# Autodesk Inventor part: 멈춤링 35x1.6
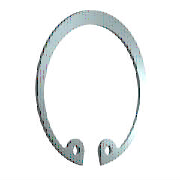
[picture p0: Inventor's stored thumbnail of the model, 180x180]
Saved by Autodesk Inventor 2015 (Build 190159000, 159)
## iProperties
IsCustomPart: 1
Created: 2012-02
Part Number: 멈춤링 35x1.6
Material: 강철, 연강
Description: 리테이닝 링(C형)
Document SubType Name: Modeling
Standard: KS B 1336
Designer: mduedu
Standards Organization: KS
Language: ko-KR
Size Designation: 35x1.6
Categories: <MemberInstance><Categories><Category DisplayName="샤프트 부품" InternalName="7f7aeb1f-a693-4053-b835-cee3144e0d98" Mnemonic="SHFT"><Category DisplayName="써클립" Inter
Density: 1 g/cm^3
Appearance: 파란색 - 벽 페인트 - 광택
Author: mduedu
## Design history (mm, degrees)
sketch "스케치1"
  geometry: L1 (0, 15.113)-(0, -73.177) reference; L2 (-45.5, 0)-(45.5, 0) reference; L3 (-4.964, 1)-(1.502, 1); L4 (0, -2.5)-(-5.307, -2.5); L5 (0, -17.5)-(-8.583, -33.888); L6 (-8.583, -33.888)-(-21.772, -26.981); L7 (-7.377, -31.585)-(-17.631, -26.214); L8 (-5.162, -32.745)-(-6.29, -34.898); L9 (5.162, -32.745)-(6.29, -34.898); C1 r 1.25 at (-7.377, -31.585); C2 r 1.25 at (7.377, -31.585); A1 r 15.875 centre (0, -18.375) between (11.82, -28.972) and (-11.82, -28.972); A2 r 18.5 centre (0, -17.5) between (6.29, -34.898) and (-6.29, -34.898); A3 r 2.5 centre (-7.377, -31.585) between (-5.162, -32.745) and (-8.668, -29.444); A4 r 2.5 centre (-9.959, -27.303) between (-11.82, -28.972) and (-8.668, -29.444); A5 r 2.5 centre (9.959, -27.303) between (8.668, -29.444) and (11.82, -28.972); A6 r 2.5 centre (7.377, -31.585) between (8.668, -29.444) and (5.162, -32.745); 3 further points
  constraints: 15 point on circle, 14 end point, 9 symmetric about line, 8 centre point, 6 tangent, 4 coincident, 4 point on line, 3 perpendicular, 1 parallel, 4 other
  dimensions: "d8" = 0.875 distance of A1.centre L5.start (= 0.25 x SRB1); "d38" = 3.5 distance between parallel lines of L4 L3 (= SRB1); "d39" = 17.5 distance from line of L5.start L2 (= 0.5 x WD); "d43" = 18.5 radius of A2 (= 0.5 x ND); "d45" = 2.6 distance between parallel lines of L7 L6 (= 0.5 x SRB2); "d46" = 2.5 radius of A4 (= SD5); "d47" = 6.29 distance from line of L1 L8.end (= 0.17 x ND); "d48" = 2.5 diameter of C1 (= SD5); "d49" = 2.5 radius of A3 (= SD5)
extrude "본체" new body sketch "스케치1" distance "d2" = 1.6 (= SD); taper "d3" = 0 deg
workaxis "Work Axis1"
workaxis "Work Axis2"
workplane "Work Plane1"
body "Solid1"
other parameters: "WD" = 35 [user parameter; used in 3 equation terms], "SD" = 1.6 [user parameter; used in 1 equation term], "SRB1" = 3.5 [user parameter; used in 2 equation terms], "ND" = 37 [user parameter; used in 2 equation terms], "SRB2" = 5.2 [user parameter; used in 1 equation term], "SD5" = 2.5 [user parameter; used in 3 equation terms], "d50" = 0, "d51" = 0, "d52" = 0, "d53" = 0, "WDMIN" = 34 [user parameter], "SD6" = 37.8 [user parameter], "WDMAX" = 35 (= WD) [user parameter], "NND" = 35 (= WD) [user parameter]
